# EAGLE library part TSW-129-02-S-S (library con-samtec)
THROUGH-HOLE .025" SQ POST HEADER Source: Samtec TSW.pdf
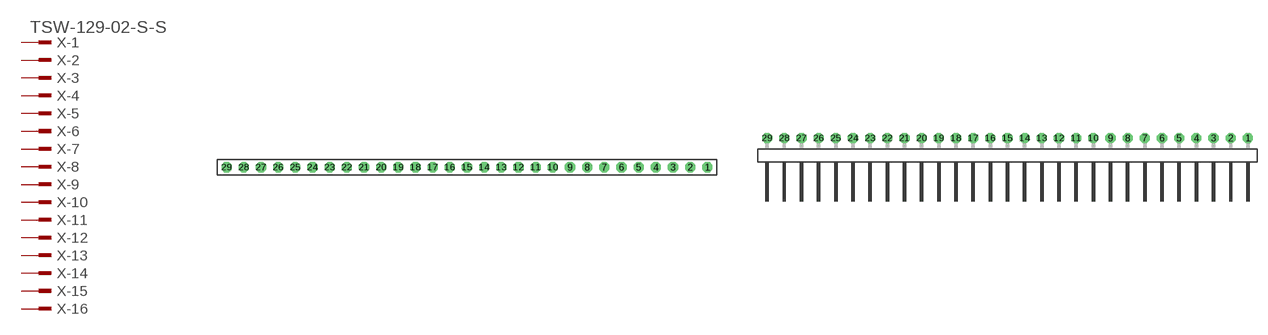
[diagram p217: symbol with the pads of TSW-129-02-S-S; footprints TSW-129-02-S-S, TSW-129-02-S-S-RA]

Designator prefix X; gates -1=MPINV -2=MPIN -3=MPIN -4=MPIN -5=MPIN -6=MPIN -7=MPIN -8=MPIN -9=MPIN -10=MPIN -11=MPIN -12=MPIN -13=MPIN -14=MPIN -15=MPIN -16=MPIN -17=MPIN -18=MPIN -19=MPIN -20=MPIN -21=MPIN -22=MPIN -23=MPIN -24=MPIN -25=MPIN -26=MPIN -27=MPIN -28=MPIN -29=MPIN

## TSW-129-02-S-S (OC_FARNELL: unknown; OC_NEWARK: unknown)  [TSW-129-02-S-S]
1  -1:1  pas
2  -2:1  pas
3  -3:1  pas
4  -4:1  pas
5  -5:1  pas
6  -6:1  pas
7  -7:1  pas
8  -8:1  pas
9  -9:1  pas
10  -10:1  pas
11  -11:1  pas
12  -12:1  pas
13  -13:1  pas
14  -14:1  pas
15  -15:1  pas
16  -16:1  pas
17  -17:1  pas
18  -18:1  pas
19  -19:1  pas
20  -20:1  pas
21  -21:1  pas
22  -22:1  pas
23  -23:1  pas
24  -24:1  pas
25  -25:1  pas
26  -26:1  pas
27  -27:1  pas
28  -28:1  pas
29  -29:1  pas

## TSW-129-02-S-S-RA (OC_FARNELL: unknown; OC_NEWARK: unknown)  [TSW-129-02-S-S-RA]
Pads as for TSW-129-02-S-S

## Footprint TSW-129-02-S-S (pad centres in mm)
THROUGH-HOLE .025" SQ POST HEADER Source: Samtec TSW.pdf
drill 1 pad 1.5 octagon: 1 35.56,0; 2 33.02,0; 3 30.48,0; 4 27.94,0; 5 25.4,0; 6 22.86,0; 7 20.32,0; 8 17.78,0; 9 15.24,0; 10 12.7,0; 11 10.16,0; 12 7.62,0; 13 5.08,0; 14 2.54,0; 15 0,0; 16 -2.54,0; 17 -5.08,0; 18 -7.62,0; 19 -10.16,0; 20 -12.7,0; 21 -15.24,0; 22 -17.78,0; 23 -20.32,0; 24 -22.86,0; 25 -25.4,0; 26 -27.94,0; 27 -30.48,0; 28 -33.02,0; 29 -35.56,0

## Footprint TSW-129-02-S-S-RA (pad centres in mm)
THROUGH-HOLE .025" SQ POST HEADER Source: Samtec TSW.pdf
drill 1 pad 1.5 octagon: 1 35.56,1.524; 2 33.02,1.524; 3 30.48,1.524; 4 27.94,1.524; 5 25.4,1.524; 6 22.86,1.524; 7 20.32,1.524; 8 17.78,1.524; 9 15.24,1.524; 10 12.7,1.524; 11 10.16,1.524; 12 7.62,1.524; 13 5.08,1.524; 14 2.54,1.524; 15 0,1.524; 16 -2.54,1.524; 17 -5.08,1.524; 18 -7.62,1.524; 19 -10.16,1.524; 20 -12.7,1.524; 21 -15.24,1.524; 22 -17.78,1.524; 23 -20.32,1.524; 24 -22.86,1.524; 25 -25.4,1.524; 26 -27.94,1.524; 27 -30.48,1.524; 28 -33.02,1.524; 29 -35.56,1.524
